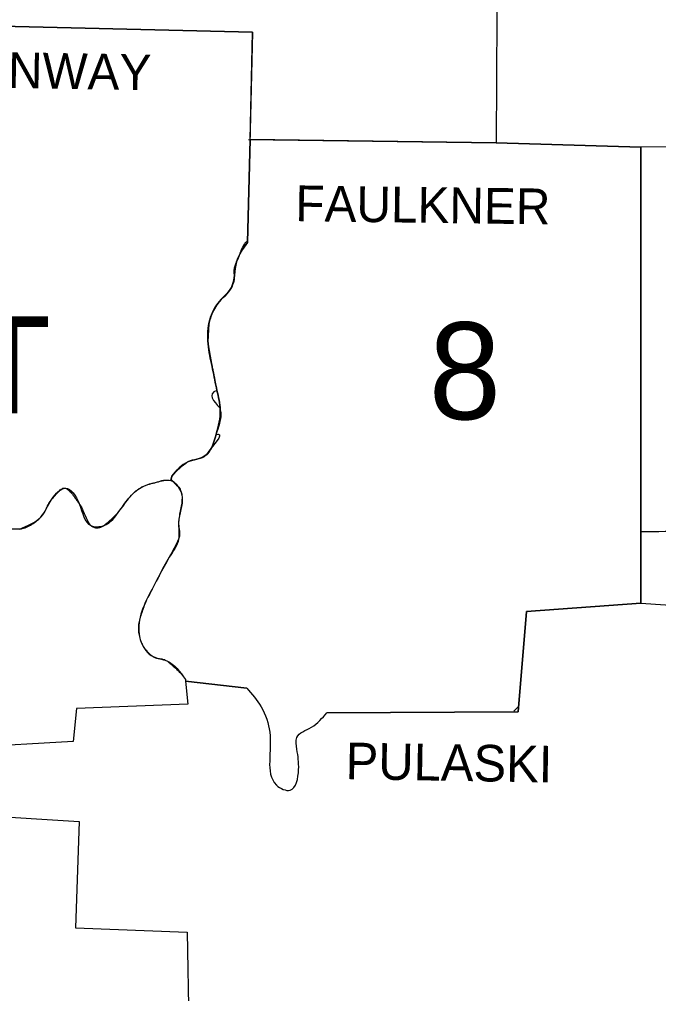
# Model space of a CAD drawing. Extents: x -13171 to 18763, y -8840 to 11152.
# Drawn here: x 13066 to 13801, y 7625 to 8746 of the extents above; entities that cross this region are included whole.
import ezdxf

# ---------------------------------------------------------------- set-up
doc = ezdxf.new("R2010")
doc.units = 0
for name, color, linetype in [('Level 1', 7, 'Continuous'), ('Level 2', 7, 'Continuous'), ('Level 3', 7, 'Continuous'), ('Level 48', 7, 'Continuous')]:
    doc.layers.add(name, color=color, linetype=linetype)

msp = doc.modelspace()

# ---------------------------------------------------------------- linework, layer by layer
at = {"layer": 'Level 1'}
for points in [[(13715.784347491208, 10314.944979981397), (13717.79049171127, 10076.2138209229), (13701.15757587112, 10075.235414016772), (13704.092796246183, 9831.612116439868), (13635.604319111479, 9821.828048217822), (13641.474760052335, 9756.274791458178), (13664.956523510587, 9725.944180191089), (13662.99970985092, 9648.650041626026), (13529.936382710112, 9643.758007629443), (13525.044348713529, 9524.392375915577), (13403.72190337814, 9520.478748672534), (13397.851462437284, 9375.67453968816), (13404.70031013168, 9363.933657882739), (13407.635530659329, 9133.029648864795), (13617.014589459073, 9119.331953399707), (13614.079369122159, 8603.711560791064), (13780.408528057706, 8598.819526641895), (13780.408528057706, 8074.393472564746), (13649.302014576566, 8064.6094043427), (13639.517946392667, 7949.157399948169), (13419.37641246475, 7948.178993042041)], [(13617.014589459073, 9119.331953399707), (14119.915693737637, 9116.396732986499), (14162.96559352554, 9136.943276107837), (14160.030373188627, 8754.386210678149), (14130.67816863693, 8741.666921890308), (14104.261184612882, 8719.163565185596), (14095.455523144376, 8710.35790371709), (14094.477116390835, 8600.776340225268), (13780.408528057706, 8598.819526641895)], [(12884.687301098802, 8741.72555171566), (13334.255019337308, 8730.904446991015), (13328.384578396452, 8489.23796307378)], [(13329.362985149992, 8607.625188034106), (13614.079369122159, 8603.711560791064)], [(13066.17155143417, 8159.514865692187), (12662.089535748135, 8172.265026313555)], [(13780.408528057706, 8074.393472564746), (13837.15612338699, 8070.47984524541), (13838.134530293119, 7696.7284411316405), (13787.257375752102, 7484.414161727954), (13895.860532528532, 7479.52212750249), (13894.844193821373, 7292.515822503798)], [(13327.406171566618, 7976.552790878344), (13256.960880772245, 7984.380045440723), (13259.896101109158, 7957.963061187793), (13131.724808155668, 7953.07102719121), (13127.811180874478, 7914.913161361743), (13007.46714229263, 7908.064313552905), (13000.61829463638, 7839.575836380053), (13018.229617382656, 7830.7701749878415), (13018.229617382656, 7785.763461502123)], [(13634.62591220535, 7950.135806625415), (13639.517946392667, 7955.027840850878)], [(13018.229617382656, 7830.219821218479), (13134.660028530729, 7822.942920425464), (13130.74640124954, 7700.642068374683), (13258.917694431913, 7695.7500342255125), (13260.874508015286, 7589.103690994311), (13321.53573062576, 7584.211657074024), (13321.53573062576, 7565.621927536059), (13378.283326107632, 7561.708300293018), (13380.240139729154, 7493.219822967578), (13509.389839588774, 7493.219822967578), (13513.303466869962, 7425.709752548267), (13632.669098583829, 7419.83931172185), (13631.689211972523, 7292.454043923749)]]:
    msp.add_lwpolyline(points, dxfattribs=at)
for points in [[(13328.384578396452, 8489.23796307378), (13315.665289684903, 8466.734606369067), (13309.79484882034, 8437.382401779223), (13294.140339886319, 8418.792672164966), (13284.35627170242, 8397.267722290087), (13283.377864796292, 8368.893924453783), (13288.269898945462, 8343.455347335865), (13293.16193298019, 8318.995176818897), (13297.07556026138, 8296.491820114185), (13292.18352622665, 8268.118022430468), (13279.464237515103, 8243.6578519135), (13259.896101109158, 8236.809004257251), (13241.306371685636, 8220.176088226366)], [(13066.17155143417, 8159.514865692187), (13090.63172179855, 8173.212561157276), (13103.35101035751, 8193.75910420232), (13119.00551944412, 8206.478392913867), (13134.660028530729, 8188.867070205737), (13148.357723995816, 8163.428492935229), (13163.033826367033, 8163.428492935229), (13181.623555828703, 8181.039815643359), (13193.364437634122, 8196.694324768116), (13208.040539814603, 8208.435206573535), (13223.695048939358, 8213.327240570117), (13240.327964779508, 8215.284054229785), (13253.047253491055, 8196.694324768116), (13249.133626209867, 8167.342120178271), (13249.133626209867, 8147.773983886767), (13238.37115111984, 8127.2274407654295), (13226.630269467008, 8105.702490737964), (13213.91098075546, 8081.242320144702), (13204.12691257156, 8054.825336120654), (13206.083726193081, 8029.386758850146), (13219.78142165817, 8012.7538430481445), (13235.43593074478, 8007.861808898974), (13256.960880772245, 7986.336859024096)], [(13780.006038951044, 8156.495384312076), (13837.15612338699, 8158.5364587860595), (13890.968498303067, 8160.493272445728), (13925.212737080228, 8150.709204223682), (13964.349009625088, 8137.989915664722), (14010.334130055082, 8132.119474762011), (14042.62155509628, 8119.400186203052), (14080.779420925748, 8099.832049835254), (14129.69976188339, 8108.637711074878), (14167.857627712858, 8118.421779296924), (14217.756375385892, 8131.141068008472), (14250.04380031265, 8144.838763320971), (14287.223259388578, 8156.579645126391), (14324.4027185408, 8151.68761112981), (14366.474211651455, 8143.860356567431), (14392.891195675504, 8128.205847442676), (14440.83312968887, 8135.054695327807), (14440.83312968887, 8195.715917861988)], [(13327.406171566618, 7976.552790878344), (13344.039087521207, 7955.027840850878), (13353.823155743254, 7925.675636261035), (13353.823155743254, 7892.409804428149), (13361.650410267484, 7865.014413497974), (13377.304919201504, 7859.143972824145), (13387.088987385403, 7882.625736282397), (13385.132173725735, 7906.107499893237), (13385.132173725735, 7919.805195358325), (13401.765089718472, 7931.5460771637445), (13419.37641246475, 7948.178993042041)]]:
    msp.add_spline(points, degree=3, dxfattribs=at)
at = {"layer": 'Level 48'}
for p, q in [((13331.259748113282, 8607.599115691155), (13328.384578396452, 8489.23796307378)), ((13614.079369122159, 8603.711560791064), (13331.259748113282, 8607.599115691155)), ((13283.961104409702, 8395.408390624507), (13282.5790305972, 8374.849939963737)), ((13282.5790305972, 8374.849939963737), (13283.377864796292, 8368.893924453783)), ((13283.37786479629, 8368.893924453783), (13288.269898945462, 8343.455347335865)), ((13259.896101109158, 8236.809004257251), (13259.42487114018, 8236.457071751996)), ((13272.01458843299, 8240.174933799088), (13259.896101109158, 8236.809004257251)), ((13241.306371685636, 8220.176088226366), (13240.327964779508, 8215.284054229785)), ((13240.327964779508, 8215.284054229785), (13241.306371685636, 8220.176088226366)), ((13241.306371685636, 8220.176088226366), (13240.327964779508, 8215.284054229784)), ((12662.089535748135, 8172.265026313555), (13066.17155143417, 8159.514865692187)), ((13780.006038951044, 8156.495384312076), (13780.408528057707, 8156.508870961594)), ((13256.960880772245, 7986.336859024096), (13256.960880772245, 7984.380045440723)), ((13256.960880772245, 7986.336859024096), (13256.960880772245, 7984.380045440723)), ((13256.960880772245, 7984.380045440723), (13327.406171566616, 7976.552790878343))]:
    msp.add_line(p, q, dxfattribs=at)
for points in [[(13328.384578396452, 8489.23796307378), (13331.259748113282, 8607.599115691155), (13334.255019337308, 8730.904446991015), (12884.687301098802, 8741.72555171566)], [(13780.408528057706, 8156.508870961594), (13780.408528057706, 8598.819526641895), (13614.079369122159, 8603.711560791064)], [(13419.37641246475, 7948.178993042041), (13639.517946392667, 7949.157399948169), (13649.302014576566, 8064.6094043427), (13780.408528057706, 8074.393472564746), (13780.408528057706, 8156.495384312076)], [(13780.408528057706, 8156.495384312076), (13780.006038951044, 8156.495384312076)]]:
    msp.add_lwpolyline(points, dxfattribs=at)
for points in [[(13241.306371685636, 8220.176088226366), (13259.896101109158, 8236.809004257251), (13279.464237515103, 8243.6578519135), (13292.18352622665, 8268.118022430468), (13297.07556026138, 8296.491820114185), (13293.16193298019, 8318.995176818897), (13288.269898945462, 8343.455347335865), (13283.377864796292, 8368.893924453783), (13284.35627170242, 8397.267722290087), (13294.140339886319, 8418.792672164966), (13309.79484882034, 8437.382401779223), (13315.665289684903, 8466.734606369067), (13328.384578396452, 8489.23796307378)], [(13328.384578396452, 8489.23796307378), (13327.262407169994, 8489.678058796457), (13326.0362788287, 8489.003283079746), (13324.731343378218, 8487.404446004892), (13323.37275082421, 8485.072357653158)], [(13309.655158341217, 8437.110931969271), (13308.10029977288, 8434.589943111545), (13306.259696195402, 8432.258781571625), (13302.073033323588, 8427.918403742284), (13297.798728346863, 8423.594725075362), (13294.140339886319, 8418.792672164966)], [(13285.1331570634, 8400.231750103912), (13284.35627170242, 8397.267722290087), (13283.961104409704, 8395.408390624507)], [(13293.16193298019, 8318.995176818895), (13293.16193298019, 8318.995176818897), (13296.766712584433, 8298.558144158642)], [(13292.183526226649, 8268.118022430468), (13292.18352622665, 8268.118022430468), (13284.869185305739, 8250.52062048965)], [(13259.424871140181, 8236.457071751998), (13254.580107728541, 8232.781608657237), (13249.85086427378, 8228.926485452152), (13243.283914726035, 8222.532860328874), (13241.306371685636, 8220.176088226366)], [(13066.17155143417, 8159.514865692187), (13067.759199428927, 8159.719017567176), (13069.345527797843, 8160.0325157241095), (13072.508626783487, 8160.96833453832), (13078.757401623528, 8163.940747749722), (13084.82829395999, 8168.124643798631), (13087.769039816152, 8170.574816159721), (13090.63172179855, 8173.212561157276), (13092.802977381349, 8175.623811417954), (13094.543555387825, 8178.147963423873), (13097.261836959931, 8183.398922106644), (13099.844883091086, 8188.6933360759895), (13103.35101035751, 8193.75910420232), (13105.207653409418, 8195.921565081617), (13107.151717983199, 8198.243879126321), (13111.184508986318, 8202.721189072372), (13115.214177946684, 8205.897278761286), (13117.15433996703, 8206.593067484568), (13118.092890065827, 8206.647145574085), (13118.552674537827, 8206.59188652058), (13119.00551944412, 8206.478392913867), (13123.116088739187, 8203.887704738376), (13127.073308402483, 8199.44294403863), (13130.910260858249, 8194.11307709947), (13132.793975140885, 8191.419030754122), (13134.660028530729, 8188.867070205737), (13135.742378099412, 8187.344386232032), (13138.430150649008, 8182.524881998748), (13141.29730722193, 8175.8196419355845), (13144.27024831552, 8169.278471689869), (13146.111622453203, 8166.234138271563), (13147.176201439, 8164.797361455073), (13148.357723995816, 8163.428492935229), (13151.538241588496, 8161.486303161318), (13155.531947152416, 8160.956096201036), (13159.607566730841, 8161.662087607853), (13163.033826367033, 8163.428492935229), (13167.96301795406, 8167.443900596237), (13172.741058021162, 8171.698888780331), (13177.312914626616, 8176.221509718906), (13181.623555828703, 8181.039815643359), (13184.626822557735, 8184.931846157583), (13187.430474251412, 8188.921025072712), (13190.265887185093, 8192.883226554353), (13193.364437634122, 8196.694324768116), (13200.120203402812, 8203.248068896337), (13203.901138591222, 8206.038859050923), (13208.040539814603, 8208.435206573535), (13211.875063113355, 8210.077001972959), (13215.782239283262, 8211.31728618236), (13219.73219300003, 8212.339539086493), (13223.695048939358, 8213.327240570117), (13227.806149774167, 8214.520125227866), (13232.001054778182, 8215.61795192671), (13240.327964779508, 8215.284054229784)], [(13240.327964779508, 8215.284054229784), (13240.327964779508, 8215.284054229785), (13242.956957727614, 8213.981093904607), (13249.330060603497, 8207.719152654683), (13251.98297352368, 8202.337632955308), (13252.730405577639, 8199.511002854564), (13253.047253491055, 8196.694324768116), (13252.642797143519, 8189.369860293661), (13251.404842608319, 8182.043122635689), (13250.009686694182, 8174.703934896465), (13249.464500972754, 8171.02649196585), (13249.133626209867, 8167.342120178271), (13249.14629643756, 8164.886763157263), (13249.370891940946, 8162.404944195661), (13250.024768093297, 8157.420181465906), (13250.233073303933, 8152.504354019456), (13249.900705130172, 8150.108704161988), (13249.133626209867, 8147.773983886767), (13243.929716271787, 8137.322216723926), (13238.37115111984, 8127.2274407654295), (13226.630269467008, 8105.702490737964), (13213.91098075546, 8081.242320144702), (13210.93623892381, 8074.825422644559), (13208.380315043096, 8068.225881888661), (13206.143706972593, 8061.530314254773), (13204.12691257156, 8054.825336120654), (13203.400298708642, 8051.75503931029), (13202.970945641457, 8048.609507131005), (13202.96448062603, 8042.180621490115), (13204.028434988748, 8035.714448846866), (13204.937106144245, 8032.522307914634), (13206.083726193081, 8029.386758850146), (13208.55802283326, 8024.452407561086), (13211.691219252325, 8020.078395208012), (13215.445093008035, 8016.2003357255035), (13217.542839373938, 8014.42716766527), (13219.78142165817, 8012.7538430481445), (13221.618347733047, 8011.731510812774), (13223.584728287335, 8011.061619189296), (13227.715451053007, 8010.309035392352), (13231.792786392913, 8009.555846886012), (13235.43593074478, 8007.861808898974), (13238.477052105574, 8005.531126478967), (13241.462383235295, 8003.127968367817), (13247.176968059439, 7998.043498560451), (13252.402271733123, 7992.486946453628), (13256.960880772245, 7986.336859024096)], [(13327.406171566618, 7976.552790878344), (13344.039087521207, 7955.027840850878), (13353.823155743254, 7925.675636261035), (13353.823155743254, 7892.409804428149), (13361.650410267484, 7865.014413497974), (13377.304919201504, 7859.143972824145), (13387.088987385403, 7882.625736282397), (13385.132173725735, 7906.107499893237), (13385.132173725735, 7919.805195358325), (13401.765089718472, 7931.5460771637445), (13419.37641246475, 7948.178993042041)]]:
    msp.add_spline(points, degree=3, dxfattribs=at)
for points, degree in [([(13323.37275082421, 8485.072357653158), (13320.686217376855, 8479.931385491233), (13317.836927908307, 8471.693445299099), (13315.665289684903, 8466.734606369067), (13311.431862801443, 8457.06776508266), (13314.265438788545, 8446.239762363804), (13309.79484882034, 8437.382401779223), (13309.748949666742, 8437.291464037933), (13309.702380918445, 8437.200977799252), (13309.65515834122, 8437.110931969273)], 3), ([(13294.140339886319, 8418.792672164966), (13290.572709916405, 8412.831645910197), (13287.116456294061, 8406.837810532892), (13285.133157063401, 8400.231750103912)], 2), ([(13288.269898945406, 8343.455347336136), (13288.269898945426, 8343.455347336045), (13288.269898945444, 8343.455347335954), (13288.269898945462, 8343.455347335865), (13289.89454126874, 8335.299465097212), (13291.53555135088, 8327.18136118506), (13293.16193298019, 8318.995176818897)], 3), ([(13296.766712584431, 8298.558144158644), (13296.871507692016, 8297.869334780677), (13296.974471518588, 8297.180556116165), (13297.07556026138, 8296.491820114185), (13298.463407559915, 8287.036163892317), (13294.972949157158, 8277.575534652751), (13292.183526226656, 8268.118022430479)], 3), ([(13284.869185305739, 8250.52062048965), (13283.35793698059, 8248.113477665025), (13281.587740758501, 8245.818404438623), (13279.464237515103, 8243.6578519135), (13277.416931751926, 8241.574826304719), (13274.786853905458, 8240.712172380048), (13272.014588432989, 8240.174933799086)], 3)]:
    msp.add_open_spline(points, degree=degree, dxfattribs=at)

# ---------------------------------------------------------------- texts
at = {"layer": 'Level 2'}
for s, height, rotation, p in [('CONWAY', 41.081345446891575, 359.0371361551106, (12970.287683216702, 8668.28641064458)), ('FAULKNER', 41.09308632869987, 359.24862226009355, (13383.175360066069, 8513.69813343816)), ('PULASKI', 42.07344995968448, 359.0530472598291, (13440.901362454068, 7871.863261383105))]:
    msp.add_text(s, height=height, rotation=rotation, dxfattribs=at).set_placement(p)
at = {"layer": 'Level 3'}
for s, p in [('DISTRICT', (12414.55261092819, 8292.578192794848)), ('8', (13536.785230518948, 8285.72934498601))]:
    msp.add_text(s, height=111.53837717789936, dxfattribs=at).set_placement(p)

doc.saveas('drawing.dxf')
